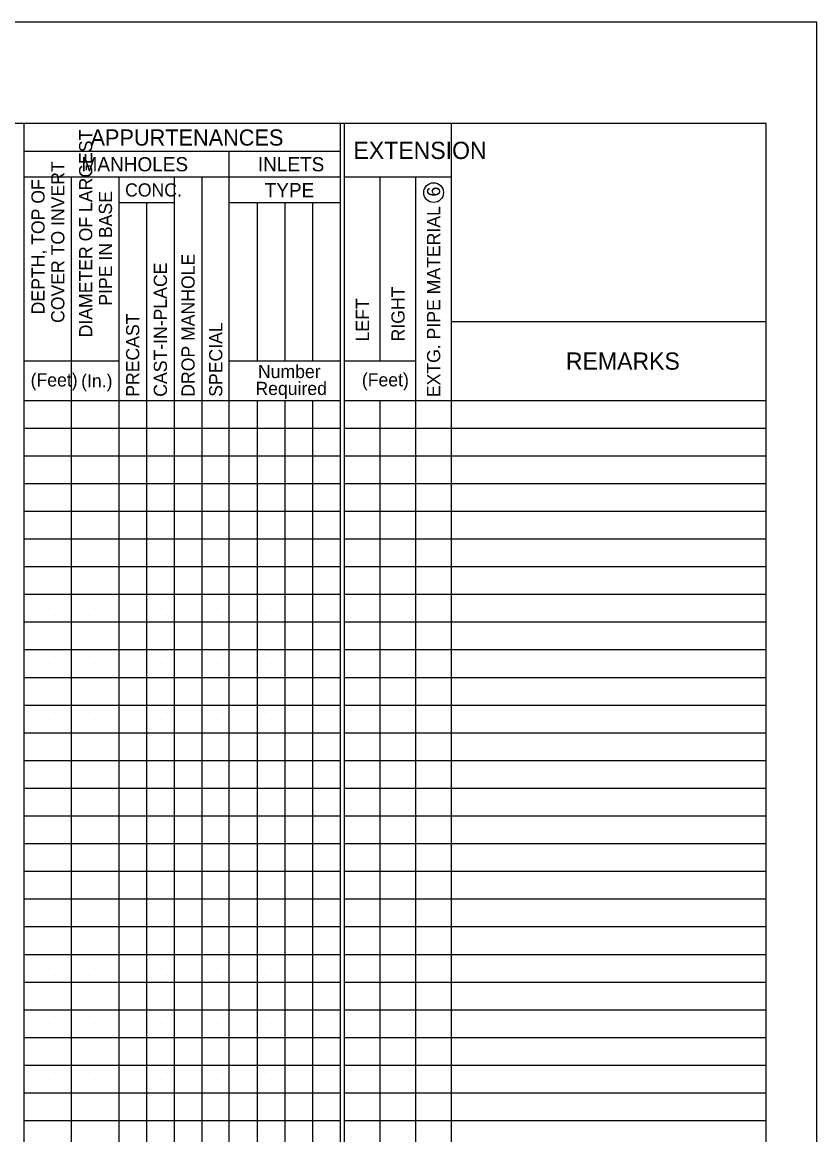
# Model space of a CAD drawing. Extents: x -1700 to 0, y 0 to 1100.
# Drawn here: x -392 to 0, y 551 to 1100 of the extents above; entities that cross this region are included whole.
import ezdxf

# ---------------------------------------------------------------- set-up
doc = ezdxf.new("R2010")
doc.units = 0
for name, color, linetype in [('#plot_shape', 7, 'Continuous'), ('P_ODOT_PLAN_Border', 7, 'Continuous'), ('P_ODOT_PLAN_General', 7, 'Continuous'), ('P_RDWY_PLAN_NotesTx', 7, 'Continuous')]:
    doc.layers.add(name, color=color, linetype=linetype)

msp = doc.modelspace()

# ---------------------------------------------------------------- linework, layer by layer
at = {"layer": '#plot_shape'}
msp.add_lwpolyline([(-1700, 0), (0, 0), (0, 1100), (-1700, 1100)], close=True, dxfattribs=at)
at = {"layer": 'P_ODOT_PLAN_Border'}
msp.add_lwpolyline([(-1625, 50), (-25, 50), (-25, 1050), (-1625, 1050)], close=True, dxfattribs=at)
at = {"layer": 'P_ODOT_PLAN_General'}
for p, q in [((-390.9, 312.45), (-390.9, 1050)), ((-234.83, 312.45), (-234.83, 1050)), ((-232.88, 312.45), (-232.88, 1050)), ((-180.2, 312.45), (-180.2, 1050)), ((-234.83, 1036.34), (-390.9, 1036.34)), ((-289.75, 312.45), (-289.75, 1036.34)), ((-234.83, 1023.66), (-390.9, 1023.66)), ((-367.5, 312.45), (-367.5, 1023.66)), ((-344.1, 312.45), (-344.1, 1023.66)), ((-316.78, 312.45), (-316.78, 1023.66)), ((-303.12, 312.45), (-303.12, 1023.66)), ((-180.2, 1023.66), (-232.88, 1023.66)), ((-215.32, 932.93), (-215.32, 1023.66)), ((-197.76, 312.45), (-197.76, 1023.66)), ((-316.78, 1010.98), (-344.1, 1010.98)), ((-330.44, 312.45), (-330.44, 1010.98)), ((-234.83, 1010.98), (-289.75, 1010.98)), ((-275.81, 932.93), (-275.81, 1010.98)), ((-262.15, 932.93), (-262.15, 1010.98)), ((-248.49, 932.93), (-248.49, 1010.98)), ((-180.2, 952.44), (-25, 952.44)), ((-344.1, 932.93), (-390.9, 932.93)), ((-234.83, 932.93), (-289.75, 932.93)), ((-197.76, 932.93), (-232.88, 932.93)), ((-390.9, 913.42), (-234.83, 913.42)), ((-275.81, 312.45), (-275.81, 913.42)), ((-262.15, 312.45), (-262.15, 913.42)), ((-248.49, 312.45), (-248.49, 913.42)), ((-232.88, 913.42), (-25, 913.42)), ((-215.32, 312.45), (-215.32, 913.42)), ((-379.06, 906.59), (-379.06, 906.59)), ((-355.66, 906.59), (-355.66, 906.59)), ((-337.27, 906.59), (-337.27, 906.59)), ((-323.61, 906.59), (-323.61, 906.59)), ((-309.95, 906.59), (-309.95, 906.59)), ((-296.3, 906.59), (-296.3, 906.59)), ((-282.64, 906.59), (-282.64, 906.59)), ((-268.98, 906.59), (-268.98, 906.59)), ((-255.32, 906.59), (-255.32, 906.59)), ((-241.66, 906.59), (-241.66, 906.59)), ((-224.1, 906.59), (-224.1, 906.59)), ((-206.54, 906.59), (-206.54, 906.59)), ((-188.98, 906.59), (-188.98, 906.59)), ((-175.74, 906.59), (-175.74, 906.59)), ((-234.83, 899.76), (-390.9, 899.76)), ((-25, 899.76), (-232.88, 899.76)), ((-379.06, 892.93), (-379.06, 892.93)), ((-355.66, 892.93), (-355.66, 892.93)), ((-337.27, 892.93), (-337.27, 892.93)), ((-323.61, 892.93), (-323.61, 892.93)), ((-309.95, 892.93), (-309.95, 892.93)), ((-296.3, 892.93), (-296.3, 892.93)), ((-282.64, 892.93), (-282.64, 892.93)), ((-268.98, 892.93), (-268.98, 892.93)), ((-255.32, 892.93), (-255.32, 892.93)), ((-241.66, 892.93), (-241.66, 892.93)), ((-224.1, 892.93), (-224.1, 892.93)), ((-206.54, 892.93), (-206.54, 892.93)), ((-188.98, 892.93), (-188.98, 892.93)), ((-175.74, 892.93), (-175.74, 892.93)), ((-234.83, 886.1), (-390.9, 886.1)), ((-25, 886.1), (-232.88, 886.1)), ((-379.06, 879.27), (-379.06, 879.27)), ((-355.66, 879.27), (-355.66, 879.27)), ((-337.27, 879.27), (-337.27, 879.27)), ((-323.61, 879.27), (-323.61, 879.27)), ((-309.95, 879.27), (-309.95, 879.27)), ((-296.3, 879.27), (-296.3, 879.27)), ((-282.64, 879.27), (-282.64, 879.27)), ((-268.98, 879.27), (-268.98, 879.27)), ((-255.32, 879.27), (-255.32, 879.27)), ((-241.66, 879.27), (-241.66, 879.27)), ((-224.1, 879.27), (-224.1, 879.27)), ((-206.54, 879.27), (-206.54, 879.27)), ((-188.98, 879.27), (-188.98, 879.27)), ((-175.74, 879.27), (-175.74, 879.27)), ((-234.83, 872.44), (-390.9, 872.44)), ((-25, 872.44), (-232.88, 872.44)), ((-379.06, 865.61), (-379.06, 865.61)), ((-355.66, 865.61), (-355.66, 865.61)), ((-337.27, 865.61), (-337.27, 865.61)), ((-323.61, 865.61), (-323.61, 865.61)), ((-309.95, 865.61), (-309.95, 865.61)), ((-296.3, 865.61), (-296.3, 865.61)), ((-282.64, 865.61), (-282.64, 865.61)), ((-268.98, 865.61), (-268.98, 865.61)), ((-255.32, 865.61), (-255.32, 865.61)), ((-241.66, 865.61), (-241.66, 865.61)), ((-224.1, 865.61), (-224.1, 865.61)), ((-206.54, 865.61), (-206.54, 865.61)), ((-188.98, 865.61), (-188.98, 865.61)), ((-175.74, 865.61), (-175.74, 865.61)), ((-234.83, 858.78), (-390.9, 858.78)), ((-25, 858.78), (-232.88, 858.78)), ((-379.06, 851.95), (-379.06, 851.95)), ((-355.66, 851.95), (-355.66, 851.95)), ((-337.27, 851.95), (-337.27, 851.95)), ((-323.61, 851.95), (-323.61, 851.95)), ((-309.95, 851.95), (-309.95, 851.95)), ((-296.3, 851.95), (-296.3, 851.95)), ((-282.64, 851.95), (-282.64, 851.95)), ((-268.98, 851.95), (-268.98, 851.95)), ((-255.32, 851.95), (-255.32, 851.95)), ((-241.66, 851.95), (-241.66, 851.95)), ((-224.1, 851.95), (-224.1, 851.95)), ((-206.54, 851.95), (-206.54, 851.95)), ((-188.98, 851.95), (-188.98, 851.95)), ((-175.74, 851.95), (-175.74, 851.95)), ((-234.83, 845.12), (-390.9, 845.12)), ((-25, 845.12), (-232.88, 845.12)), ((-379.06, 838.29), (-379.06, 838.29)), ((-355.66, 838.29), (-355.66, 838.29)), ((-337.27, 838.29), (-337.27, 838.29)), ((-323.61, 838.29), (-323.61, 838.29)), ((-309.95, 838.29), (-309.95, 838.29)), ((-296.3, 838.29), (-296.3, 838.29)), ((-282.64, 838.29), (-282.64, 838.29)), ((-268.98, 838.29), (-268.98, 838.29)), ((-255.32, 838.29), (-255.32, 838.29)), ((-241.66, 838.29), (-241.66, 838.29)), ((-224.1, 838.29), (-224.1, 838.29)), ((-206.54, 838.29), (-206.54, 838.29)), ((-188.98, 838.29), (-188.98, 838.29)), ((-175.74, 838.29), (-175.74, 838.29)), ((-234.83, 831.47), (-390.9, 831.47)), ((-25, 831.47), (-232.88, 831.47)), ((-379.06, 824.64), (-379.06, 824.64)), ((-355.66, 824.64), (-355.66, 824.64)), ((-337.27, 824.64), (-337.27, 824.64)), ((-323.61, 824.64), (-323.61, 824.64)), ((-309.95, 824.64), (-309.95, 824.64)), ((-296.3, 824.64), (-296.3, 824.64)), ((-282.64, 824.64), (-282.64, 824.64)), ((-268.98, 824.64), (-268.98, 824.64)), ((-255.32, 824.64), (-255.32, 824.64)), ((-241.66, 824.64), (-241.66, 824.64)), ((-224.1, 824.64), (-224.1, 824.64)), ((-206.54, 824.64), (-206.54, 824.64)), ((-188.98, 824.64), (-188.98, 824.64)), ((-175.74, 824.64), (-175.74, 824.64)), ((-234.83, 817.81), (-390.9, 817.81)), ((-25, 817.81), (-232.88, 817.81)), ((-379.06, 810.98), (-379.06, 810.98)), ((-355.66, 810.98), (-355.66, 810.98)), ((-337.27, 810.98), (-337.27, 810.98)), ((-323.61, 810.98), (-323.61, 810.98)), ((-309.95, 810.98), (-309.95, 810.98)), ((-296.3, 810.98), (-296.3, 810.98)), ((-282.64, 810.98), (-282.64, 810.98)), ((-268.98, 810.98), (-268.98, 810.98)), ((-255.32, 810.98), (-255.32, 810.98)), ((-241.66, 810.98), (-241.66, 810.98)), ((-224.1, 810.98), (-224.1, 810.98)), ((-206.54, 810.98), (-206.54, 810.98)), ((-188.98, 810.98), (-188.98, 810.98)), ((-175.74, 810.98), (-175.74, 810.98)), ((-234.83, 804.15), (-390.9, 804.15)), ((-25, 804.15), (-232.88, 804.15)), ((-379.06, 797.32), (-379.06, 797.32)), ((-355.66, 797.32), (-355.66, 797.32)), ((-337.27, 797.32), (-337.27, 797.32)), ((-323.61, 797.32), (-323.61, 797.32)), ((-309.95, 797.32), (-309.95, 797.32)), ((-296.3, 797.32), (-296.3, 797.32)), ((-282.64, 797.32), (-282.64, 797.32)), ((-268.98, 797.32), (-268.98, 797.32)), ((-255.32, 797.32), (-255.32, 797.32)), ((-241.66, 797.32), (-241.66, 797.32)), ((-224.1, 797.32), (-224.1, 797.32)), ((-206.54, 797.32), (-206.54, 797.32)), ((-188.98, 797.32), (-188.98, 797.32)), ((-175.74, 797.32), (-175.74, 797.32)), ((-234.83, 790.49), (-390.9, 790.49)), ((-25, 790.49), (-232.88, 790.49)), ((-379.06, 783.66), (-379.06, 783.66)), ((-355.66, 783.66), (-355.66, 783.66)), ((-337.27, 783.66), (-337.27, 783.66)), ((-323.61, 783.66), (-323.61, 783.66)), ((-309.95, 783.66), (-309.95, 783.66)), ((-296.3, 783.66), (-296.3, 783.66)), ((-282.64, 783.66), (-282.64, 783.66)), ((-268.98, 783.66), (-268.98, 783.66)), ((-255.32, 783.66), (-255.32, 783.66)), ((-241.66, 783.66), (-241.66, 783.66)), ((-224.1, 783.66), (-224.1, 783.66)), ((-206.54, 783.66), (-206.54, 783.66)), ((-188.98, 783.66), (-188.98, 783.66)), ((-175.74, 783.66), (-175.74, 783.66)), ((-234.83, 776.83), (-390.9, 776.83)), ((-25, 776.83), (-232.88, 776.83)), ((-379.06, 770), (-379.06, 770)), ((-355.66, 770), (-355.66, 770)), ((-337.27, 770), (-337.27, 770)), ((-323.61, 770), (-323.61, 770)), ((-309.95, 770), (-309.95, 770)), ((-296.3, 770), (-296.3, 770)), ((-282.64, 770), (-282.64, 770)), ((-268.98, 770), (-268.98, 770)), ((-255.32, 770), (-255.32, 770)), ((-241.66, 770), (-241.66, 770)), ((-224.1, 770), (-224.1, 770)), ((-206.54, 770), (-206.54, 770)), ((-188.98, 770), (-188.98, 770)), ((-175.74, 770), (-175.74, 770)), ((-234.83, 763.17), (-390.9, 763.17)), ((-25, 763.17), (-232.88, 763.17)), ((-379.06, 756.34), (-379.06, 756.34)), ((-355.66, 756.34), (-355.66, 756.34)), ((-337.27, 756.34), (-337.27, 756.34)), ((-323.61, 756.34), (-323.61, 756.34)), ((-309.95, 756.34), (-309.95, 756.34)), ((-296.3, 756.34), (-296.3, 756.34)), ((-282.64, 756.34), (-282.64, 756.34)), ((-268.98, 756.34), (-268.98, 756.34)), ((-255.32, 756.34), (-255.32, 756.34)), ((-241.66, 756.34), (-241.66, 756.34)), ((-224.1, 756.34), (-224.1, 756.34)), ((-206.54, 756.34), (-206.54, 756.34)), ((-188.98, 756.34), (-188.98, 756.34)), ((-175.74, 756.34), (-175.74, 756.34)), ((-234.83, 749.52), (-390.9, 749.52)), ((-25, 749.52), (-232.88, 749.52)), ((-379.06, 742.69), (-379.06, 742.69)), ((-355.66, 742.69), (-355.66, 742.69)), ((-337.27, 742.69), (-337.27, 742.69)), ((-323.61, 742.69), (-323.61, 742.69)), ((-309.95, 742.69), (-309.95, 742.69)), ((-296.3, 742.69), (-296.3, 742.69)), ((-282.64, 742.69), (-282.64, 742.69)), ((-268.98, 742.69), (-268.98, 742.69)), ((-255.32, 742.69), (-255.32, 742.69)), ((-241.66, 742.69), (-241.66, 742.69)), ((-224.1, 742.69), (-224.1, 742.69)), ((-206.54, 742.69), (-206.54, 742.69)), ((-188.98, 742.69), (-188.98, 742.69)), ((-175.74, 742.69), (-175.74, 742.69)), ((-234.83, 735.86), (-390.9, 735.86)), ((-25, 735.86), (-232.88, 735.86)), ((-379.06, 729.03), (-379.06, 729.03)), ((-355.66, 729.03), (-355.66, 729.03)), ((-337.27, 729.03), (-337.27, 729.03)), ((-323.61, 729.03), (-323.61, 729.03)), ((-309.95, 729.03), (-309.95, 729.03)), ((-296.3, 729.03), (-296.3, 729.03)), ((-282.64, 729.03), (-282.64, 729.03)), ((-268.98, 729.03), (-268.98, 729.03)), ((-255.32, 729.03), (-255.32, 729.03)), ((-241.66, 729.03), (-241.66, 729.03)), ((-224.1, 729.03), (-224.1, 729.03)), ((-206.54, 729.03), (-206.54, 729.03)), ((-188.98, 729.03), (-188.98, 729.03)), ((-175.74, 729.03), (-175.74, 729.03)), ((-234.83, 722.2), (-390.9, 722.2)), ((-25, 722.2), (-232.88, 722.2)), ((-379.06, 715.37), (-379.06, 715.37)), ((-355.66, 715.37), (-355.66, 715.37)), ((-337.27, 715.37), (-337.27, 715.37)), ((-323.61, 715.37), (-323.61, 715.37)), ((-309.95, 715.37), (-309.95, 715.37)), ((-296.3, 715.37), (-296.3, 715.37)), ((-282.64, 715.37), (-282.64, 715.37)), ((-268.98, 715.37), (-268.98, 715.37)), ((-255.32, 715.37), (-255.32, 715.37)), ((-241.66, 715.37), (-241.66, 715.37)), ((-224.1, 715.37), (-224.1, 715.37)), ((-206.54, 715.37), (-206.54, 715.37)), ((-188.98, 715.37), (-188.98, 715.37)), ((-175.74, 715.37), (-175.74, 715.37)), ((-234.83, 708.54), (-390.9, 708.54)), ((-25, 708.54), (-232.88, 708.54)), ((-379.06, 701.71), (-379.06, 701.71)), ((-355.66, 701.71), (-355.66, 701.71)), ((-337.27, 701.71), (-337.27, 701.71)), ((-323.61, 701.71), (-323.61, 701.71)), ((-309.95, 701.71), (-309.95, 701.71)), ((-296.3, 701.71), (-296.3, 701.71)), ((-282.64, 701.71), (-282.64, 701.71)), ((-268.98, 701.71), (-268.98, 701.71)), ((-255.32, 701.71), (-255.32, 701.71)), ((-241.66, 701.71), (-241.66, 701.71)), ((-224.1, 701.71), (-224.1, 701.71)), ((-206.54, 701.71), (-206.54, 701.71)), ((-188.98, 701.71), (-188.98, 701.71)), ((-175.74, 701.71), (-175.74, 701.71)), ((-234.83, 694.88), (-390.9, 694.88)), ((-25, 694.88), (-232.88, 694.88)), ((-379.06, 688.05), (-379.06, 688.05)), ((-355.66, 688.05), (-355.66, 688.05)), ((-337.27, 688.05), (-337.27, 688.05)), ((-323.61, 688.05), (-323.61, 688.05)), ((-309.95, 688.05), (-309.95, 688.05)), ((-296.3, 688.05), (-296.3, 688.05)), ((-282.64, 688.05), (-282.64, 688.05)), ((-268.98, 688.05), (-268.98, 688.05)), ((-255.32, 688.05), (-255.32, 688.05)), ((-241.66, 688.05), (-241.66, 688.05)), ((-224.1, 688.05), (-224.1, 688.05)), ((-206.54, 688.05), (-206.54, 688.05)), ((-188.98, 688.05), (-188.98, 688.05)), ((-175.74, 688.05), (-175.74, 688.05)), ((-234.83, 681.22), (-390.9, 681.22)), ((-25, 681.22), (-232.88, 681.22)), ((-379.06, 674.39), (-379.06, 674.39)), ((-355.66, 674.39), (-355.66, 674.39)), ((-337.27, 674.39), (-337.27, 674.39)), ((-323.61, 674.39), (-323.61, 674.39)), ((-309.95, 674.39), (-309.95, 674.39)), ((-296.3, 674.39), (-296.3, 674.39)), ((-282.64, 674.39), (-282.64, 674.39)), ((-268.98, 674.39), (-268.98, 674.39)), ((-255.32, 674.39), (-255.32, 674.39)), ((-241.66, 674.39), (-241.66, 674.39)), ((-224.1, 674.39), (-224.1, 674.39)), ((-206.54, 674.39), (-206.54, 674.39)), ((-188.98, 674.39), (-188.98, 674.39)), ((-175.74, 674.39), (-175.74, 674.39)), ((-234.83, 667.56), (-390.9, 667.56)), ((-25, 667.56), (-232.88, 667.56)), ((-379.06, 660.74), (-379.06, 660.74)), ((-355.66, 660.74), (-355.66, 660.74)), ((-337.27, 660.74), (-337.27, 660.74)), ((-323.61, 660.74), (-323.61, 660.74)), ((-309.95, 660.74), (-309.95, 660.74)), ((-296.3, 660.74), (-296.3, 660.74)), ((-282.64, 660.74), (-282.64, 660.74)), ((-268.98, 660.74), (-268.98, 660.74)), ((-255.32, 660.74), (-255.32, 660.74)), ((-241.66, 660.74), (-241.66, 660.74)), ((-224.1, 660.74), (-224.1, 660.74)), ((-206.54, 660.74), (-206.54, 660.74)), ((-188.98, 660.74), (-188.98, 660.74)), ((-175.74, 660.74), (-175.74, 660.74)), ((-234.83, 653.91), (-390.9, 653.91)), ((-25, 653.91), (-232.88, 653.91)), ((-379.06, 647.08), (-379.06, 647.08)), ((-355.66, 647.08), (-355.66, 647.08)), ((-337.27, 647.08), (-337.27, 647.08)), ((-323.61, 647.08), (-323.61, 647.08)), ((-309.95, 647.08), (-309.95, 647.08)), ((-296.3, 647.08), (-296.3, 647.08)), ((-282.64, 647.08), (-282.64, 647.08)), ((-268.98, 647.08), (-268.98, 647.08)), ((-255.32, 647.08), (-255.32, 647.08)), ((-241.66, 647.08), (-241.66, 647.08)), ((-224.1, 647.08), (-224.1, 647.08)), ((-206.54, 647.08), (-206.54, 647.08)), ((-188.98, 647.08), (-188.98, 647.08)), ((-175.74, 647.08), (-175.74, 647.08)), ((-234.83, 640.25), (-390.9, 640.25)), ((-25, 640.25), (-232.88, 640.25)), ((-379.06, 633.42), (-379.06, 633.42)), ((-355.66, 633.42), (-355.66, 633.42)), ((-337.27, 633.42), (-337.27, 633.42)), ((-323.61, 633.42), (-323.61, 633.42)), ((-309.95, 633.42), (-309.95, 633.42)), ((-296.29, 633.42), (-296.29, 633.42)), ((-282.64, 633.42), (-282.64, 633.42)), ((-268.98, 633.42), (-268.98, 633.42)), ((-255.32, 633.42), (-255.32, 633.42)), ((-241.66, 633.42), (-241.66, 633.42)), ((-224.1, 633.42), (-224.1, 633.42)), ((-206.54, 633.42), (-206.54, 633.42)), ((-188.98, 633.42), (-188.98, 633.42)), ((-175.74, 633.42), (-175.74, 633.42)), ((-234.83, 626.59), (-390.9, 626.59)), ((-25, 626.59), (-232.88, 626.59)), ((-379.06, 619.76), (-379.06, 619.76)), ((-355.66, 619.76), (-355.66, 619.76)), ((-337.27, 619.76), (-337.27, 619.76)), ((-323.61, 619.76), (-323.61, 619.76)), ((-309.95, 619.76), (-309.95, 619.76)), ((-296.29, 619.76), (-296.29, 619.76)), ((-282.64, 619.76), (-282.64, 619.76)), ((-268.98, 619.76), (-268.98, 619.76)), ((-255.32, 619.76), (-255.32, 619.76)), ((-241.66, 619.76), (-241.66, 619.76)), ((-224.1, 619.76), (-224.1, 619.76)), ((-206.54, 619.76), (-206.54, 619.76)), ((-188.98, 619.76), (-188.98, 619.76)), ((-175.74, 619.76), (-175.74, 619.76)), ((-234.83, 612.93), (-390.9, 612.93)), ((-25, 612.93), (-232.88, 612.93)), ((-379.06, 606.1), (-379.06, 606.1)), ((-355.66, 606.1), (-355.66, 606.1)), ((-337.27, 606.1), (-337.27, 606.1)), ((-323.61, 606.1), (-323.61, 606.1)), ((-309.95, 606.1), (-309.95, 606.1)), ((-296.29, 606.1), (-296.29, 606.1)), ((-282.64, 606.1), (-282.64, 606.1)), ((-268.98, 606.1), (-268.98, 606.1)), ((-255.32, 606.1), (-255.32, 606.1)), ((-241.66, 606.1), (-241.66, 606.1)), ((-224.1, 606.1), (-224.1, 606.1)), ((-206.54, 606.1), (-206.54, 606.1)), ((-188.98, 606.1), (-188.98, 606.1)), ((-175.74, 606.1), (-175.74, 606.1)), ((-234.83, 599.27), (-390.9, 599.27)), ((-25, 599.27), (-232.88, 599.27)), ((-379.06, 592.44), (-379.06, 592.44)), ((-355.66, 592.44), (-355.66, 592.44)), ((-337.27, 592.44), (-337.27, 592.44)), ((-323.61, 592.44), (-323.61, 592.44)), ((-309.95, 592.44), (-309.95, 592.44)), ((-296.29, 592.44), (-296.29, 592.44)), ((-282.64, 592.44), (-282.64, 592.44)), ((-268.98, 592.44), (-268.98, 592.44)), ((-255.32, 592.44), (-255.32, 592.44)), ((-241.66, 592.44), (-241.66, 592.44)), ((-224.1, 592.44), (-224.1, 592.44)), ((-206.54, 592.44), (-206.54, 592.44)), ((-188.98, 592.44), (-188.98, 592.44)), ((-175.74, 592.44), (-175.74, 592.44)), ((-234.83, 585.61), (-390.9, 585.61)), ((-25, 585.61), (-232.88, 585.61)), ((-379.06, 578.79), (-379.06, 578.79)), ((-355.66, 578.79), (-355.66, 578.79)), ((-337.27, 578.79), (-337.27, 578.79)), ((-323.61, 578.79), (-323.61, 578.79)), ((-309.95, 578.79), (-309.95, 578.79)), ((-296.29, 578.79), (-296.29, 578.79)), ((-282.64, 578.79), (-282.64, 578.79)), ((-268.98, 578.79), (-268.98, 578.79)), ((-255.32, 578.79), (-255.32, 578.79)), ((-241.66, 578.79), (-241.66, 578.79)), ((-224.1, 578.79), (-224.1, 578.79)), ((-206.54, 578.79), (-206.54, 578.79)), ((-188.98, 578.79), (-188.98, 578.79)), ((-175.74, 578.79), (-175.74, 578.79)), ((-234.83, 571.96), (-390.9, 571.96)), ((-25, 571.96), (-232.88, 571.96)), ((-379.06, 565.13), (-379.06, 565.13)), ((-355.66, 565.13), (-355.66, 565.13)), ((-337.27, 565.13), (-337.27, 565.13)), ((-323.61, 565.13), (-323.61, 565.13)), ((-309.95, 565.13), (-309.95, 565.13)), ((-296.29, 565.13), (-296.29, 565.13)), ((-282.64, 565.13), (-282.64, 565.13)), ((-268.98, 565.13), (-268.98, 565.13)), ((-255.32, 565.13), (-255.32, 565.13)), ((-241.66, 565.13), (-241.66, 565.13)), ((-224.1, 565.13), (-224.1, 565.13)), ((-206.54, 565.13), (-206.54, 565.13)), ((-188.98, 565.13), (-188.98, 565.13)), ((-175.74, 565.13), (-175.74, 565.13)), ((-234.83, 558.3), (-390.9, 558.3)), ((-25, 558.3), (-232.88, 558.3))]:
    msp.add_line(p, q, dxfattribs=at)
at = {"layer": 'P_RDWY_PLAN_NotesTx'}
for p, q in [((-282.64, 937.93), (-282.64, 937.93)), ((-268.98, 937.93), (-268.98, 937.93)), ((-255.32, 937.93), (-255.32, 937.93)), ((-241.66, 937.93), (-241.66, 937.93)), ((-337.41, 915.34), (-337.41, 915.34)), ((-323.75, 915.34), (-323.75, 915.34)), ((-310.1, 915.34), (-310.1, 915.34)), ((-296.44, 915.34), (-296.44, 915.34))]:
    msp.add_line(p, q, dxfattribs=at)
msp.add_circle((-189, 1016), 4.88, dxfattribs=at)

# ---------------------------------------------------------------- texts
for s, p in [('DIAMETER OF LARGEST', (-357.34, 944.64)), ('COVER TO INVERT', (-371.1, 951.74)), ('DEPTH, TOP OF', (-380.85, 955.97)), ('PIPE IN BASE', (-347.59, 960.26)), ('6', (-185.75, 1014.09)), ('EXTG. PIPE MATERIAL', (-185.73, 915.15)), ('DROP MANHOLE', (-306.85, 915.34)), ('CAST-IN-PLACE', (-320.5, 915.34)), ('RIGHT', (-203.29, 942.63)), ('LEFT', (-220.85, 942.63)), ('PRECAST', (-334.16, 915.34)), ('SPECIAL', (-293.19, 915.34))]:
    msp.add_text(s, height=6.5, rotation=90, dxfattribs=at).set_placement(p)
for s, height, p in [('APPURTENANCES', 8, (-358.19, 1039.17)), ('EXTENSION', 8.5, (-228.51, 1032.58)), ('MANHOLES', 7, (-362.61, 1026.5)), ('INLETS', 7, (-275.67, 1026.5)), ('CONC.', 6.5, (-341.15, 1014.07)), ('TYPE', 7, (-272.29, 1013.73)), ('REMARKS', 8.5, (-123.73, 928.68)), ('(Feet)', 6.5, (-387.74, 920.4)), ('Number', 6.5, (-275.62, 924.55)), ('(Feet)', 6.5, (-224.37, 920.46)), ('(In.)', 6.5, (-362.82, 919.96)), ('Required', 6.5, (-276.86, 916.21))]:
    msp.add_text(s, height=height, dxfattribs=at).set_placement(p)

doc.saveas('drawing.dxf')
